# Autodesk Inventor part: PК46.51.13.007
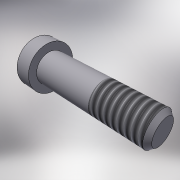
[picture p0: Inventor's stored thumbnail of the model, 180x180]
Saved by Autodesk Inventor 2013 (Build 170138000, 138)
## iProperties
Created: 2005-04
Part Number: PК46.51.13.007
Material: Stainless Steel, 440C
Document SubType Name: Modeling
Designer: =<Author>
Manufacturer: Standard
Standards Organization: Custom
Description: pin
Density: 7.75 g/cm^3
Mass: 15.0629 g
Surface Area: 10.79 cm^2
Volume: 1.9436 cm^3
Author: PVitaliy
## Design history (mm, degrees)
sketch "Эскиз2"
  geometry: L1 (0, 0)-(47.162, 0); L2 (0, 0)-(0, 6); L3 (0, 6)-(5, 6); L4 (5, 6)-(5, 4); L5 (5, 4)-(33, 4); L6 (33, 4)-(33, 0); L7 (0, 0)-(33, 0)
  constraints: 14 end point, 3 parallel, 3 perpendicular, 1 horizontal, 1 point on line, 1 other
  dimensions: "d0" = 12 diameter of L3 L1; "d1" = 8 diameter of L5 L1; "d2" = 33 distance between parallel lines of L6 L2; "d3" = 28 distance between parallel lines of L4 L6
revolve "Вращение1" sketch "Эскиз2" stored, may be unused: angle "d4" = 90 deg
chamfer "Фаска1" distance "d5" = 1; stored, may be unused: second distance "d6" = 2, angle "d7" = 45 deg
feature "Резьба1" dims "d8" = 13, "d9" = 0
chamfer "Фаска2" distance "d10" = 1; stored, may be unused: second distance "d11" = 2, angle "d12" = 45 deg
body "Solid1"
